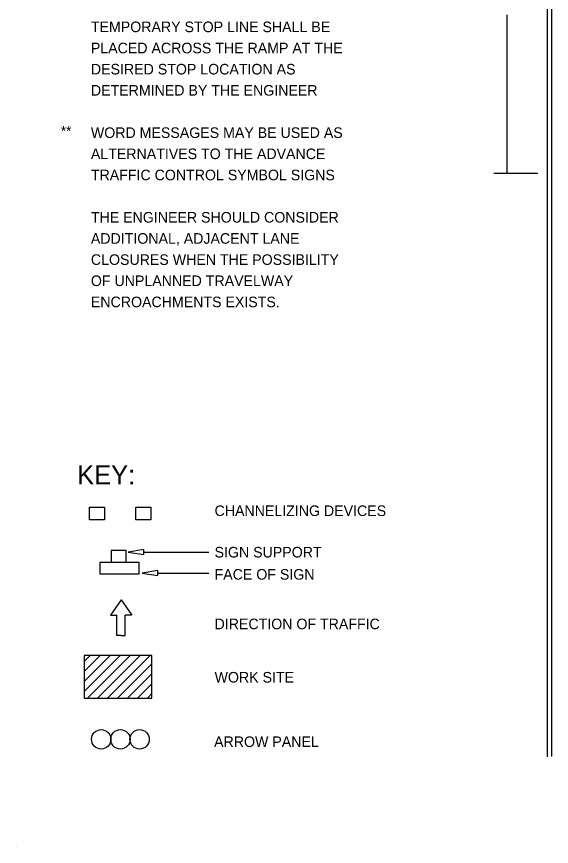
# Model space of a CAD drawing. Extents: x 612.48 to 619.85, y 611.03 to 621.01.
# Drawn here: x 612.485 to 615.514, y 612.128 to 616.834 of the extents above; entities that cross this region are included whole.
import ezdxf

# ---------------------------------------------------------------- set-up
doc = ezdxf.new("R2010")
doc.units = 0
for name, color, linetype in [('DETL-DIMS', 7, 'Continuous'), ('DETL-LINE', 7, 'Continuous'), ('DETL-NOTE', 7, 'Continuous'), ('DETL-TITL', 7, 'Continuous'), ('TTLB-TEXT', 7, 'Continuous'), ('USER-BORD', 7, 'Continuous')]:
    doc.layers.add(name, color=color, linetype=linetype)

# ---------------------------------------------------------------- blocks, each defined once
blk = doc.blocks.new('PANEL1')
at = {"layer": 'USER-BORD'}
for centre in [(0.0309, -0.0012), (0.0928, -0.0012), (0.1546, -0.0012)]:
    blk.add_circle(centre, 0.0312, dxfattribs=at)
blk = doc.blocks.new('DIR3')
at = {"layer": 'USER-BORD'}
for p, q in [((0, 0.0012), (-0.0342, -0.0477)), ((0, 0.0012), (0.0342, -0.0477)), ((-0.0342, -0.0477), (-0.0132, -0.0477)), ((-0.0132, -0.1133), (-0.0132, -0.0477)), ((0.0342, -0.0477), (0.0132, -0.0477)), ((0.0132, -0.1133), (0.0132, -0.0477)), ((-0.0011, -0.1133), (-0.0132, -0.1133)), ((-0.0011, -0.1133), (0.0011, -0.1133)), ((0.0011, -0.1133), (0.0132, -0.1133))]:
    blk.add_line(p, q, dxfattribs=at)
blk = doc.blocks.new('SIGN14')
at = {"layer": 'USER-BORD'}
for points in [[(-0.0134, 0.0182), (0.011, 0.0189), (0.011, 0.0371), (-0.0134, 0.0371)], [(-0.0314, 0.0182), (-0.0314, 0), (0.032, 0), (0.032, 0.0182)]]:
    blk.add_lwpolyline(points, close=True, dxfattribs=at)

msp = doc.modelspace()

# ---------------------------------------------------------------- linework, layer by layer
at = {"layer": 'DETL-DIMS'}
for p, q in [((615.2618, 616.8441), (615.2618, 615.9454)), ((615.1891, 615.9454), (615.4374, 615.9454)), ((613.2056, 613.797), (613.5745, 613.797)), ((613.2844, 613.6778), (613.5745, 613.6778))]:
    msp.add_line(p, q, dxfattribs=at)
for points in [[(613.2056, 613.7823), (613.2056, 613.8117), (613.1176, 613.797)], [(613.2844, 613.6631), (613.2844, 613.6925), (613.1964, 613.6778)]]:
    msp.add_lwpolyline(points, close=True, dxfattribs=at)
at = {"layer": 'DETL-LINE'}
for p, q in [((615.4908, 617.8594), (615.4908, 612.6359)), ((615.5143, 617.8602), (615.5143, 612.6367)), ((613.2517, 613.2099), (612.8682, 613.2099)), ((612.8682, 613.2099), (612.8682, 612.968)), ((612.8682, 613.1761), (612.902, 613.2099)), ((612.8682, 613.1196), (612.9585, 613.2099)), ((612.8682, 613.063), (613.0151, 613.2099)), ((612.8682, 613.0064), (613.0717, 613.2099)), ((612.8864, 612.968), (613.1282, 613.2099)), ((612.9429, 612.968), (613.1848, 613.2099)), ((612.9995, 612.968), (613.2414, 613.2099)), ((613.2517, 612.968), (613.2517, 613.2099)), ((613.0561, 612.968), (613.2517, 613.1637)), ((613.1126, 612.968), (613.2517, 613.1071)), ((613.1692, 612.968), (613.2517, 613.0505)), ((613.2258, 612.968), (613.2517, 612.994)), ((612.8682, 612.968), (613.2517, 612.968))]:
    msp.add_line(p, q, dxfattribs=at)
for points in [[(612.8985, 613.9799), (612.8985, 614.0509), (612.9829, 614.0509), (612.9829, 613.9799)], [(613.1612, 613.9799), (613.1612, 614.0509), (613.2456, 614.0509), (613.2456, 613.9799)]]:
    msp.add_lwpolyline(points, close=True, dxfattribs=at)
at = {"layer": 'TTLB-TEXT'}
msp.add_line((612.485, 612.1276), (612.485, 612.1276), dxfattribs=at)

# ---------------------------------------------------------------- block references
at = {"layer": 'DETL-LINE'}
for name, p, xscale, yscale in [('SIGN14', (613.0673, 613.6743), 3.5200000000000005, 3.5200000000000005), ('DIR3', (613.0768, 613.5237), 1.7600000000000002, 1.7600000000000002), ('PANEL1', (612.9096, 612.737), 1.7600000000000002, 1.7600000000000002)]:
    msp.add_blockref(name, p, dxfattribs=dict(at, xscale=xscale, yscale=yscale))

# ---------------------------------------------------------------- texts
at = {"layer": 'DETL-NOTE'}
for s, height, p in [('TEMPORARY STOP LINE SHALL BE', 0.06, (612.9057, 616.7456)), ('PLACED ACROSS THE RAMP AT THE', 0.06, (612.9057, 616.6256)), ('DESIRED STOP LOCATION AS', 0.06, (612.9057, 616.5056)), ('DETERMINED BY THE ENGINEER', 0.06, (612.9057, 616.3856)), ('**', 0.057, (612.7358, 616.1565)), ('WORD MESSAGES MAY BE USED AS', 0.06, (612.9057, 616.1456)), ('ALTERNATIVES TO THE ADVANCE', 0.06, (612.9057, 616.0256)), ('TRAFFIC CONTROL SYMBOL SIGNS', 0.06, (612.9057, 615.9056)), ('THE ENGINEER SHOULD CONSIDER', 0.06, (612.9057, 615.6656)), ('ADDITIONAL, ADJACENT LANE', 0.06, (612.9057, 615.5456)), ('CLOSURES WHEN THE POSSIBILITY', 0.06, (612.9057, 615.4256)), ('OF UNPLANNED TRAVELWAY', 0.06, (612.9057, 615.3056)), ('ENCROACHMENTS EXISTS.', 0.06, (612.9057, 615.1856)), ('CHANNELIZING DEVICES', 0.06, (613.6064, 614.0014)), ('SIGN SUPPORT', 0.06, (613.6064, 613.7662)), ('FACE OF SIGN', 0.06, (613.6064, 613.6406)), ('DIRECTION OF TRAFFIC', 0.06, (613.6064, 613.3593)), ('WORK SITE', 0.06, (613.6064, 613.057)), ('ARROW PANEL', 0.06, (613.6037, 612.6915))]:
    msp.add_text(s, height=height, dxfattribs=at).set_placement(p)
at = {"layer": 'DETL-TITL'}
msp.add_text('KEY:', height=0.108, dxfattribs=at).set_placement((612.8276, 614.181))

doc.saveas('drawing.dxf')
